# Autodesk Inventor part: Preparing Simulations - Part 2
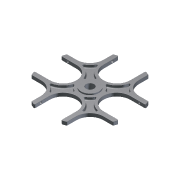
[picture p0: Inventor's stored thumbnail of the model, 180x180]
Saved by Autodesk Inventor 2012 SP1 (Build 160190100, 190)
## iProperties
Created: 2004-06
Part Number: Preparing Simulations - Part 2
Document SubType Name: Modeling
Designer: brent
Manufacturer: Standard
Standards Organization: Custom
Density: 2.71 g/cm^3
Material: Aluminum-6061
Mass: 73.4254 g
Surface Area: 338.43 cm^2
Volume: 73.4254 cm^3
Author: Autodesk, Inc.
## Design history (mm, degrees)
sketch "Sketch1"
  geometry: C1 r 100 at (0, 0)
  constraints: 1 centre point
  dimensions: "d0" = 200 diameter of C1
extrude "Extrusion1" new body sketch "Sketch1" stored distance "d1" = 8; taper "d2" = 0 deg
sketch "Sketch2"
  geometry: L1 (-30, 95.394)-(-30, 60.394); L2 (30, 60.394)-(30, 95.394); A1 r 100 centre (0, 0) between (-30, 95.394) and (30, 95.394) reference; A2 r 30 centre (0, 60.394) between (-30, 60.394) and (30, 60.394)
  constraints: 4 end point, 4 point on circle, 2 tangent, 1 centre point, 1 parallel, 1 vertical, 1 vertical alignment
  dimensions: "d3" = 60 distance between parallel lines of L2 L1; "d4" = 35 distance of L2.start L2.end
extrude "Extrusion2" cut sketch "Sketch2" stored distance "d5" = 8; taper "d6" = 0 deg
sketch "Sketch5"
  geometry: L1 (0, 35)-(8, 35) reference; L2 (0, 0)-(8, 0) reference; L3 (0, -30.394)-(0, 35) reference; 2 further points
  constraints: 1 midpoint, 1 vertical alignment
  dimensions: "d30" = 20 distance from line of L2 point (4, 20)
hole "Hole2" sketch "Sketch5" at (4, 20) diameter "d31" = 5; stored, may be unused: countersink angle "d35" = 90 deg, drill point angle "d37" = 118 deg; dims "d32" = 6, "d33" = 4, "d34" = 2, "d36" = 5
mirror "Mirror1"
pattern_circular "Circular Pattern2" dims "d39" = 360 deg
sketch "Sketch7"
  geometry: L1 (-30, 60.394)-(-30, 95.394) reference; L2 (-95.394, 30)-(-60.394, 30) reference; L3 (-40, 91.652)-(-40, 70); L4 (-70, 40)-(-91.652, 40); A1 r 100 centre (0, 0) between (-30, 95.394) and (-95.394, 30) reference; A2 r 30 centre (-70, 70) between (-70, 40) and (-40, 70)
  constraints: 4 end point, 4 point on circle, 2 tangent, 1 centre point
  dimensions: "d41" = 10 distance between parallel lines of L1 L3 (= d42); "d42" = 10 distance between parallel lines of L2 L4; "d43" = 30 radius of A2
extrude "Extrusion5" cut sketch "Sketch7" stored distance "d44" = 6; taper "d45" = 0 deg
pattern_circular "Circular Pattern3" dims angle "d47" = 360 deg
sketch "Sketch4"
  geometry: C1 r 20 at (0, 0); A1 r 100 centre (0, 0) between (95.394, 30) and (30, 95.394) reference
  constraints: 1 centre point, 1 coincident
  dimensions: "d13" = 40 diameter of C1
extrude "Extrusion4" join sketch "Sketch4" stored distance "d14" = 14; taper "d15" = 0 deg
hole "Hole1" diameter "d18" = 18; stored, may be unused: countersink angle "d22" = 90 deg, drill point angle "d24" = 118 deg; dims "d16" = 10, "d17" = 10, "d19" = 6, "d20" = 4, "d21" = 2, "d23" = 8
sketch "Sketch8"
  geometry: C1 r 20 at (0, 0) reference; A1 r 30 centre (0, 60.394) between (-30, 60.394) and (30, 60.394) reference; A2 r 30 centre (-70, 70) between (-70, 40) and (-40, 70) reference; A3 r 30 centre (-60.394, 0) between (-60.394, -30) and (-60.394, 30) reference; A4 r 100 centre (0, 0) between (95.394, 30) and (91.652, 40) reference; A5 r 36 centre (0, 60.394) between (-35.941, 58.338) and (-6.913, 25.064); A6 r 36 centre (-70, 70) between (-58.338, 35.941) and (-35.941, 58.338); A7 r 36 centre (-60.394, 0) between (-25.064, 6.913) and (-58.338, 35.941); A8 r 26 centre (0, 0) between (-25.064, 6.913) and (-6.913, 25.064)
  constraints: 8 point on circle, 4 centre point, 3 coincident, 1 concentric
  dimensions: "d49" = 6 radial gap between concentric circles of A5 A1; "d50" = 6 radial gap between concentric circles of A2 A6 (= d49); "d51" = 6 radial gap between concentric circles of A3 A7 (= d49); "d52" = 6 radial gap between concentric circles of A8 C1 (= d49)
extrude "Extrusion6" cut sketch "Sketch8" distance "d53" = 6; taper "d54" = 0 deg
fillet "Fillet1" dims "d55" = 2
pattern_circular "Circular Pattern4" dims angle "d57" = 360 deg
fillet "Fillet3" dims "d60" = 2
fillet "Fillet2" dims "d59" = 0.5
body "Solid1"
other parameters: "sa_0" = 4712.38898, "sa_1" = 0
